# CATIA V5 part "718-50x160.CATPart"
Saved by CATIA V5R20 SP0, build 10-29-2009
Part number: 718-50x160
Definition: NONE
Nomenclature: 718-50x160
Source: Unknown
Description: 718-50x160
Bounding box of the stored display mesh (mm): x 0 to 207, y -31.5 to 31.5, z -31.5 to 31.5
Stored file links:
  C:\Users\Utente\Desktop\IO LAVORO\3D X SITO CF\X SITO\718\718-50x160.CATPart
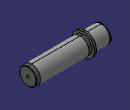
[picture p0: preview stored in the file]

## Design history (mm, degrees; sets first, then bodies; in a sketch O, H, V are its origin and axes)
Body1 "718-50x160" (main body)
  Solid1: solid without history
